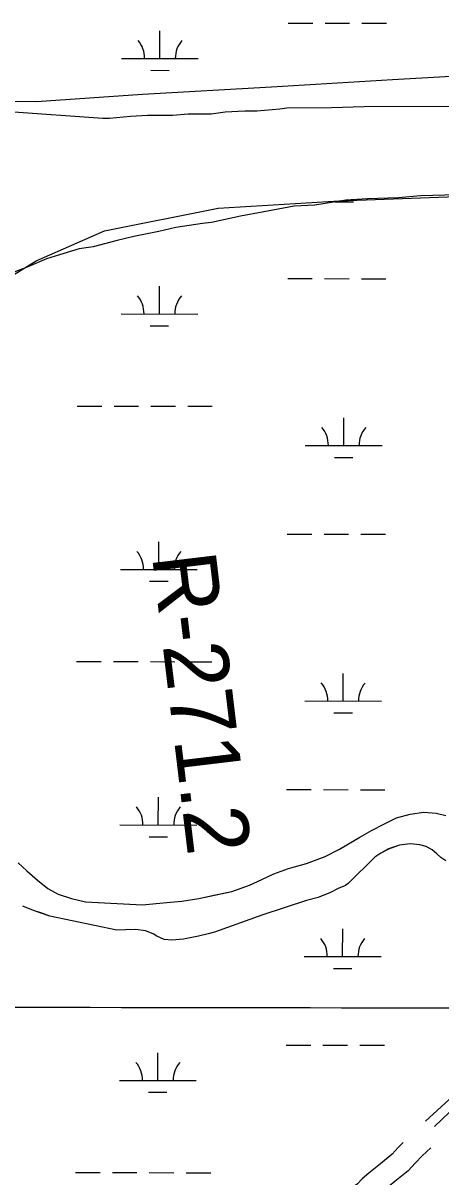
# Model space of a CAD drawing. Extents: x 3219052 to 3256913, y 800770 to 826146.
# Drawn here: x 3227815 to 3228359, y 818080 to 819582 of the extents above; entities that cross this region are included whole.
import ezdxf

# ---------------------------------------------------------------- set-up
doc = ezdxf.new("R2010")
doc.units = 0
for name, color, linetype in [('V-GRID-MAJR', 7, 'Continuous'), ('V-RIVR-RANG-IDEN', 7, 'Continuous'), ('V-ROAD-CNTR', 7, 'Continuous'), ('V-SITE-VEGE', 7, 'Continuous'), ('V-TOPO-SHOR', 7, 'Continuous'), ('V-WETL-SWMP', 7, 'Continuous')]:
    doc.layers.add(name, color=color, linetype=linetype)

msp = doc.modelspace()

# ---------------------------------------------------------------- linework, layer by layer
at = {"layer": 'V-GRID-MAJR'}
msp.add_spline([(3223238.921, 818307.868), (3228474.772, 818299.872), (3233710.625, 818292.637), (3238946.4790000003, 818286.164), (3244182.3340000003, 818280.452), (3249418.1890000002, 818275.502), (3254654.045, 818271.314), (3254654.046, 818271.314)], degree=3, dxfattribs=at)
at = {"layer": 'V-ROAD-CNTR'}
for points in [[(3228410.8688447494, 818221.3545238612), (3228405.7967447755, 818214.4668647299), (3228374.2160611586, 818184.9051391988), (3228338.7016543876, 818152.3343046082)], [(3228350.3662622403, 818145.6356813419), (3228408.5881457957, 818200.9995706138)], [(3228309.642771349, 818124.8571441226), (3228303.2705492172, 818118.2125760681), (3228295.428937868, 818109.459364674), (3228280.1265035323, 818097.0724853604), (3228264.848034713, 818084.8994706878), (3228256.434818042, 818077.5163090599), (3228250.266709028, 818071.0504359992), (3228240.320583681, 818062.8180108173), (3228235.2351730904, 818058.3360911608)], [(3228345.561130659, 818117.8008658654), (3228334.3033871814, 818107.2292102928), (3228325.275450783, 818097.8154239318), (3228316.171062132, 818087.6526353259), (3228298.911496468, 818073.6815146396), (3228284.0999652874, 818061.8805293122), (3228277.2231819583, 818055.8456909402), (3228271.993620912, 818050.3636740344)]]:
    msp.add_lwpolyline(points, dxfattribs=at)
at = {"layer": 'V-SITE-VEGE'}
for p, q in [((3227796.467, 819466.9639999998), (3227918.325, 819458.311)), ((3228059.571, 819463.9799999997), (3228077.708, 819466.634)), ((3228077.708, 819466.634), (3228103.624, 819468.0189999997)), ((3228103.624, 819468.0189999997), (3228119.176, 819468.0719999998)), ((3228119.176, 819468.0719999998), (3228148.977, 819470.767)), ((3228148.977, 819470.767), (3228158.043, 819472.094)), ((3228158.043, 819472.094), (3228216.364, 819472.2929999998)), ((3228216.364, 819472.2929999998), (3228259.128, 819473.7369999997)), ((3228259.128, 819473.737), (3228472.972, 819474.47)), ((3227918.325, 819458.311), (3227927.395, 819458.3420000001)), ((3227927.395, 819458.3420000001), (3227954.605, 819461.027)), ((3227954.605, 819461.0269999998), (3227976.631, 819462.3989999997)), ((3227976.631, 819462.399), (3228009.0330000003, 819462.51)), ((3228009.0330000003, 819462.51), (3228029.765, 819463.8779999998)), ((3228029.765, 819463.8779999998), (3228059.571, 819463.9799999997)), ((3228234.923, 819351.8279999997), (3228194.768, 819345.209)), ((3228263.429, 819353.22), (3228234.923, 819351.828)), ((3228303.603, 819354.656), (3228263.429, 819353.22)), ((3228332.107, 819357.345), (3228303.603, 819354.656)), ((3228380.052, 819358.805), (3228332.107, 819357.345)), ((3228126.111, 819335.8999999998), (3228097.615, 819330.617)), ((3228167.556, 819343.8200000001), (3228126.111, 819335.8999999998)), ((3228194.768, 819345.209), (3228167.556, 819343.8200000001)), ((3228048.397, 819321.3779999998), (3228013.424, 819316.0739999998)), ((3228060.057, 819322.7129999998), (3228048.397, 819321.3779999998)), ((3228097.615, 819330.617), (3228060.057, 819322.7129999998)), ((3227959.031, 819304.2220000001), (3227937.015, 819298.963)), ((3227991.4080000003, 819310.8139999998), (3227959.031, 819304.2220000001)), ((3228013.424, 819316.0739999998), (3227991.4080000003, 819310.8139999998)), ((3227887.801, 819288.426), (3227861.9080000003, 819280.5589999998)), ((3227905.938, 819291.0799999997), (3227887.801, 819288.426)), ((3227937.015, 819298.963), (3227905.938, 819291.0799999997)), ((3227845.078, 819275.3189999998), (3227817.901, 819263.5609999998)), ((3227861.9080000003, 819280.5589999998), (3227845.078, 819275.3189999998)), ((3227817.901, 819263.5609999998), (3227803.663, 819258.3279999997)), ((3228300.93, 818547.5269999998), (3228318.668, 818552.1039999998)), ((3228318.668, 818552.104), (3228336.813, 818554.664)), ((3228336.813, 818554.664), (3228352.656, 818553.6929999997)), ((3228352.656, 818553.6929999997), (3228365.1040000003, 818550.329)), ((3228268.441, 818530.7169999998), (3228285.591, 818539.773)), ((3228285.591, 818539.773), (3228300.93, 818547.5269999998)), ((3228226.87, 818506.4829999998), (3228253.0870000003, 818522.2959999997)), ((3228253.0870000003, 818522.2959999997), (3228268.441, 818530.7169999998)), ((3228208.1520000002, 818497.2319999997), (3228226.87, 818506.4829999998)), ((3228290.774, 818506.8329999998), (3228280.8370000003, 818501.2129999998)), ((3228304.9420000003, 818511.7029999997), (3228290.774, 818506.8329999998)), ((3228318.828, 818513.4500000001), (3228304.9420000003, 818511.7029999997)), ((3228331.316, 818512.3200000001), (3228318.828, 818513.4500000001)), ((3228339.541, 818510.153), (3228331.316, 818512.3200000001)), ((3228347.502, 818505.7559999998), (3228339.541, 818510.1529999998)), ((3228353.664, 818500.724), (3228347.502, 818505.756)), ((3228183.844, 818487.8629999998), (3228208.1520000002, 818497.2319999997)), ((3228272.698, 818496.2289999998), (3228238.091, 818462.033)), ((3228280.8370000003, 818501.2129999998), (3228272.698, 818496.2289999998)), ((3228358.929, 818495.708), (3228353.664, 818500.724)), ((3228365.102, 818491.346), (3228358.929, 818495.708)), ((3227808.079, 818488.9679999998), (3227819.492, 818478.2509999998)), ((3227819.492, 818478.2509999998), (3227833.3370000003, 818466.1460000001)), ((3228141.362, 818474.3699999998), (3228160.49, 818481.6039999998)), ((3228160.49, 818481.6039999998), (3228183.844, 818487.8629999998)), ((3227833.3370000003, 818466.1460000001), (3227846.989, 818455.611)), ((3228109.579, 818459.5609999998), (3228125.588, 818467.2989999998)), ((3228125.588, 818467.299), (3228141.362, 818474.37)), ((3228238.091, 818462.033), (3228234.4620000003, 818459.199)), ((3227846.989, 818455.611), (3227860.477, 818448.2050000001)), ((3227860.477, 818448.2050000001), (3227877.572, 818442.5179999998)), ((3228043.343, 818442.274), (3228086.414, 818451.506)), ((3228086.414, 818451.506), (3228109.579, 818459.561)), ((3228214.855, 818450.1879999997), (3228199.093, 818443.7849999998)), ((3228225.23, 818455.3529999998), (3228214.855, 818450.1879999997)), ((3228234.4620000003, 818459.199), (3228225.23, 818455.3529999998)), ((3227828.342, 818426.699), (3227814.378, 818432.546)), ((3227877.572, 818442.5179999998), (3227895.809, 818438.149)), ((3227895.809, 818438.149), (3227970.356, 818434.2769999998)), ((3227970.356, 818434.2769999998), (3227987.815, 818435.956)), ((3227987.815, 818435.956), (3228006.8370000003, 818437.605)), ((3228006.8370000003, 818437.6049999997), (3228021.609, 818439.1119999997)), ((3228021.609, 818439.112), (3228043.343, 818442.274)), ((3228183.821, 818439.6049999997), (3228126.725, 818421.253)), ((3228199.093, 818443.7849999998), (3228183.821, 818439.6049999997)), ((3227849.6550000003, 818419.5879999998), (3227828.342, 818426.699)), ((3227936.6580000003, 818400.9579999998), (3227849.6550000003, 818419.5879999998)), ((3228126.725, 818421.253), (3228063.96, 818398.5389999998)), ((3227947.843, 818401.6379999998), (3227936.6580000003, 818400.9579999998)), ((3227961.474, 818401.8279999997), (3227947.843, 818401.6379999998)), ((3227973.9590000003, 818400.2490000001), (3227961.474, 818401.828)), ((3227983.934, 818396.262), (3227973.9590000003, 818400.2490000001)), ((3227988.792, 818393.2629999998), (3227983.934, 818396.262)), ((3227998.3200000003, 818389.0649999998), (3227988.792, 818393.2629999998)), ((3228008.576, 818387.9729999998), (3227998.3200000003, 818389.0649999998)), ((3228023.573, 818389.4769999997), (3228008.576, 818387.9729999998)), ((3228043.308, 818393.3449999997), (3228023.573, 818389.4769999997)), ((3228055.872, 818396.235), (3228043.308, 818393.3449999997)), ((3228063.96, 818398.5389999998), (3228055.872, 818396.235))]:
    msp.add_line(p, q, dxfattribs=at)
at = {"layer": 'V-TOPO-SHOR'}
for points in [[(3228790.3889561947, 819487.6412589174), (3228661.164554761, 819487.9121016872), (3228582.221613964, 819497.9480559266), (3228463.8175465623, 819517.9372140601), (3228295.9991486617, 819508.418449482), (3228138.0512043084, 819498.8789973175), (3227970.232806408, 819489.3602327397), (3227832.025769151, 819479.7794054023), (3227703.709873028, 819480.0483440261)], [(3227703.1099330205, 819193.8051911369), (3227831.591329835, 819272.4998808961), (3227920.5081621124, 819311.7955068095), (3228068.6270280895, 819341.0965536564), (3228226.574972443, 819350.6360058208), (3228473.3569987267, 819359.989269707)], [(3227808.079, 818488.968), (3227819.492, 818478.251), (3227833.3370000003, 818466.1460000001), (3227846.989, 818455.611), (3227860.477, 818448.2050000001), (3227877.572, 818442.518), (3227895.809, 818438.149), (3227970.356, 818434.277), (3227987.815, 818435.956), (3228006.8370000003, 818437.605), (3228021.612, 818439.112), (3228043.343, 818442.274), (3228063.309, 818446.585), (3228086.414, 818451.508), (3228109.579, 818459.559), (3228125.588, 818467.299), (3228141.362, 818474.37), (3228160.49, 818481.604), (3228183.844, 818487.863), (3228208.1520000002, 818497.232), (3228226.87, 818506.483), (3228253.0870000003, 818522.296), (3228268.441, 818530.7170000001), (3228285.591, 818539.773), (3228300.93, 818547.527), (3228318.668, 818552.104), (3228336.813, 818554.664), (3228352.656, 818553.693), (3228365.1040000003, 818550.329)], [(3228365.102, 818491.346), (3228358.929, 818495.708), (3228353.662, 818500.724), (3228347.502, 818505.756), (3228339.541, 818510.153), (3228331.316, 818512.3200000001), (3228318.828, 818513.4500000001), (3228304.9420000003, 818511.703), (3228290.774, 818506.833), (3228280.8370000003, 818501.213), (3228272.7, 818496.229), (3228238.091, 818462.033), (3228234.4620000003, 818459.199), (3228225.23, 818455.353), (3228214.855, 818450.188), (3228199.093, 818443.783), (3228183.821, 818439.605), (3228126.725, 818421.253), (3228063.96, 818398.539), (3228055.872, 818396.235), (3228043.308, 818393.345), (3228023.573, 818389.4770000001), (3228008.576, 818387.973), (3227998.3200000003, 818389.063), (3227988.792, 818393.263), (3227983.934, 818396.262), (3227973.957, 818400.2490000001), (3227961.474, 818401.826), (3227947.843, 818401.638), (3227936.6580000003, 818400.958), (3227849.6550000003, 818419.588), (3227840.3310000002, 818422.671), (3227828.344, 818426.697), (3227814.378, 818432.546)]]:
    msp.add_lwpolyline(points, dxfattribs=at)
at = {"layer": 'V-WETL-SWMP'}
for p, q in [((3227992.867298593, 819536.1715655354), (3227992.942748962, 819572.1714542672)), ((3228160.028241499, 819582.2512716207), (3228192.0281711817, 819582.1842026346)), ((3228208.028136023, 819582.1506681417), (3228240.0280657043, 819582.0835991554)), ((3228256.0280305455, 819582.0500646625), (3228288.027960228, 819581.9829956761)), ((3227942.8674084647, 819536.276360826), (3228042.867188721, 819536.0667702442)), ((3227980.8349839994, 819520.7657640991), (3228004.8349312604, 819520.7154623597)), ((3227796.4669837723, 819466.9645471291), (3227918.323984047, 819458.3105547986)), ((3228059.5719833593, 819463.9795356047), (3228077.707983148, 819466.6335296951)), ((3228077.707983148, 819466.6335296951), (3228103.623983, 819468.0185255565)), ((3228103.623983, 819468.0185255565), (3228119.1759829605, 819468.072524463)), ((3228119.1759829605, 819468.0725244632), (3228148.9759827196, 819470.7665177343)), ((3228148.9759827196, 819470.7665177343), (3228158.0429826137, 819472.0935147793)), ((3228158.0429826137, 819472.0935147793), (3228216.363982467, 819472.2935106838)), ((3228216.363982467, 819472.2935106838), (3228259.128982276, 819473.7365053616)), ((3228259.128982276, 819473.7365053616), (3228472.9719817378, 819474.4704903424)), ((3227918.323984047, 819458.3105547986), (3227927.3959840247, 819458.3415541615)), ((3227927.3959840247, 819458.3415541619), (3227954.6039837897, 819461.0275476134)), ((3227954.6039837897, 819461.0275476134), (3227976.6319836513, 819462.3985437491)), ((3227976.6319836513, 819462.3985437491), (3228009.03198357, 819462.5095414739)), ((3228009.03198357, 819462.5095414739), (3228029.7639834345, 819463.877537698)), ((3228029.7639834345, 819463.8775376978), (3228059.5719833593, 819463.9795356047)), ((3228234.9219901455, 819351.826724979), (3228194.767990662, 819345.2087393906)), ((3228220.948458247, 819349.4492853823), (3228244.948405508, 819349.3989836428)), ((3228263.4299899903, 819353.2207206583), (3228234.9219901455, 819351.826724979)), ((3228303.6029898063, 819354.6547155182), (3228263.4299899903, 819353.2207206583)), ((3228332.105989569, 819357.3447088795), (3228303.6029898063, 819354.654715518)), ((3228380.0549893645, 819358.8047031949), (3228332.105989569, 819357.3447088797)), ((3228126.109991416, 819335.9007604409), (3228097.6149918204, 819330.6187717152)), ((3228167.5559908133, 819343.8187436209), (3228126.109991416, 819335.9007604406)), ((3228194.767990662, 819345.2087393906), (3228167.5559908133, 819343.8187436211)), ((3228048.3979925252, 819321.3777913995), (3228013.4229929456, 819316.0728031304)), ((3228060.0569924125, 819322.7137882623), (3228048.3979925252, 819321.3777913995)), ((3228097.6149918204, 819330.6187717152), (3228060.0569924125, 819322.7137882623)), ((3227959.0299938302, 819304.2218278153), (3227937.014994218, 819298.9628386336)), ((3227991.4079933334, 819310.8138139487), (3227959.0299938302, 819304.2218278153)), ((3228013.4229929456, 819316.0728031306), (3227991.4079933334, 819310.8138139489)), ((3227887.801995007, 819288.4248606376), (3227861.9089955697, 819280.5598763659)), ((3227905.9379947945, 819291.0798547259), (3227887.801995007, 819288.4248606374)), ((3227937.014994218, 819298.9628386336), (3227905.9379947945, 819291.0798547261)), ((3227845.077995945, 819275.317886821), (3227817.9019967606, 819263.5609095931)), ((3227861.9089955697, 819280.5598763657), (3227845.077995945, 819275.3178868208)), ((3227817.9019967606, 819263.5609095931), (3227803.6629971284, 819258.3279198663)), ((3228159.3310067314, 819249.5772998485), (3228191.3309364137, 819249.5102308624)), ((3228207.330901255, 819249.4766963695), (3228239.330830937, 819249.4096273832)), ((3228255.3307957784, 819249.3760928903), (3228287.3307254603, 819249.3090239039)), ((3227992.1700638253, 819203.4975937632), (3227992.2455141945, 819239.497482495)), ((3227942.1701736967, 819203.6023890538), (3228042.169953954, 819203.392798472)), ((3227980.1377492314, 819188.0917923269), (3228004.1376964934, 819188.0414905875)), ((3227885.074648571, 819083.6508998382), (3227917.074578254, 819083.5838308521)), ((3227933.0745430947, 819083.5502963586), (3227965.0744727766, 819083.4832273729)), ((3227981.074437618, 819083.4496928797), (3228013.0743673, 819083.3826238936)), ((3228029.074332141, 819083.3490894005), (3228061.0742618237, 819083.2820204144)), ((3228232.283538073, 819032.1811150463), (3228232.358988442, 819068.181003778)), ((3228182.2836479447, 819032.285910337), (3228282.283428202, 819032.0763197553)), ((3228220.2512234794, 819016.7753136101), (3228244.251170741, 819016.7250118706)), ((3228158.6337719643, 818916.9033280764), (3228190.6337016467, 818916.8362590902)), ((3228206.633666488, 818916.8027245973), (3228238.6335961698, 818916.735655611)), ((3228254.6335610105, 818916.7021211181), (3228286.6334906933, 818916.6350521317)), ((3227991.472829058, 818870.823621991), (3227991.548279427, 818906.8235107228)), ((3227941.4729389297, 818870.9284172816), (3228041.472719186, 818870.7188266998)), ((3227979.4405144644, 818855.4178205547), (3228003.440461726, 818855.3675188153)), ((3227884.377413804, 818750.976928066), (3227916.377343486, 818750.9098590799)), ((3227932.377308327, 818750.8763245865), (3227964.3772380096, 818750.8092556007)), ((3227980.3772028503, 818750.7757211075), (3228012.3771325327, 818750.7086521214)), ((3228028.377097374, 818750.6751176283), (3228060.3770270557, 818750.6080486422)), ((3228231.5863033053, 818699.5071432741), (3228231.6617536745, 818735.5070320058)), ((3228181.5864131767, 818699.6119385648), (3228281.586193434, 818699.4023479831)), ((3228219.553988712, 818684.1013418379), (3228243.5539359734, 818684.0510400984)), ((3228157.9365371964, 818584.2293563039), (3228189.9364668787, 818584.1622873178)), ((3228205.93643172, 818584.1287528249), (3228237.936361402, 818584.0616838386)), ((3228253.936326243, 818584.0281493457), (3228285.9362559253, 818583.9610803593)), ((3227990.77559429, 818538.1496502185), (3227990.8510446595, 818574.1495389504)), ((3228300.931204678, 818547.5317120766), (3228318.668204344, 818552.1097027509)), ((3228318.668204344, 818552.1097027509), (3228336.8132041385, 818554.6696970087)), ((3228336.8132041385, 818554.6696970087), (3228352.657204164, 818553.6986977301)), ((3228352.657204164, 818553.6986977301), (3228365.1052043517, 818550.3347029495)), ((3227940.7757041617, 818538.2544455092), (3228040.7754844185, 818538.0448549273)), ((3228268.44020583, 818530.7227442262), (3228285.5912052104, 818539.7797269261)), ((3228285.5912052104, 818539.7797269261), (3228300.931204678, 818547.5317120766)), ((3227978.7432796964, 818522.7438487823), (3228002.7432269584, 818522.6935470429)), ((3228226.8712074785, 818506.4887902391), (3228253.087206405, 818522.3007602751)), ((3228253.087206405, 818522.3007602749), (3228268.44020583, 818530.7227442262)), ((3228208.151208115, 818497.2378079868), (3228226.8712074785, 818506.4887902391)), ((3228290.77520731, 818506.8397855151), (3228280.8372076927, 818501.2187962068)), ((3228304.942206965, 818511.7087758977), (3228290.77520731, 818506.8397855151)), ((3228318.8272068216, 818513.455771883), (3228304.942206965, 818511.7087758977)), ((3228331.3172068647, 818512.3247731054), (3228318.8272068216, 818513.455771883)), ((3228339.542206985, 818510.1577764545), (3228331.3172068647, 818512.3247731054)), ((3228347.502207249, 818505.7617838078), (3228339.542206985, 818510.1577764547)), ((3228353.662207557, 818500.7297924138), (3228347.502207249, 818505.7617838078)), ((3228183.8442087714, 818487.8688263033), (3228208.151208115, 818497.2378079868)), ((3228272.7002080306, 818496.2348056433), (3228238.0912103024, 818462.0398690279)), ((3228280.8372076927, 818501.2187962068), (3228272.7002080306, 818496.2348056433)), ((3228358.929207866, 818495.7148010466), (3228353.662207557, 818500.7297924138)), ((3227808.078209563, 818488.9738484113), (3227819.4922102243, 818478.25686685)), ((3227819.4922102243, 818478.25686685), (3227833.337210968, 818466.1518876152)), ((3228141.3622097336, 818474.37685316), (3228160.4902092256, 818481.609838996)), ((3228160.4902092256, 818481.609838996), (3228183.8442087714, 818487.8688263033)), ((3227833.337210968, 818466.1518876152), (3227846.989211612, 818455.6159055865)), ((3228109.579210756, 818459.564881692), (3228125.5892102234, 818467.3038668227)), ((3228125.5892102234, 818467.3038668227), (3228141.3622097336, 818474.37685316)), ((3228238.0912103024, 818462.0398690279), (3228234.462210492, 818459.2038743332)), ((3227846.989211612, 818455.6159055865), (3227860.4772120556, 818448.2109179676)), ((3227860.4772120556, 818448.2109179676), (3227877.572212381, 818442.5239270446)), ((3228043.3432120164, 818442.2799168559), (3228086.414211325, 818451.5148975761)), ((3228086.414211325, 818451.5148975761), (3228109.579210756, 818459.564881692)), ((3228214.854211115, 818450.1928917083), (3228199.0932115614, 818443.789904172)), ((3228225.22921076, 818455.3578818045), (3228214.854211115, 818450.1928917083)), ((3228234.462210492, 818459.2038743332), (3228225.22921076, 818455.3578818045)), ((3227828.3432135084, 818426.7029584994), (3227814.3792131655, 818432.5529489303)), ((3227877.572212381, 818442.5239270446), (3227895.809212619, 818438.1559336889)), ((3227895.809212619, 818438.1559336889), (3227970.357212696, 818434.2819358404)), ((3227970.357212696, 818434.2819358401), (3227987.8152125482, 818435.961931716)), ((3227987.8152125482, 818435.9619317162), (3228006.837212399, 818437.6109275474)), ((3228006.837212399, 818437.6109275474), (3228021.6112122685, 818439.1179239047)), ((3228021.6112122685, 818439.1179239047), (3228043.3432120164, 818442.2799168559)), ((3228183.8212118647, 818439.6119126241), (3228126.725213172, 818421.2589491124)), ((3228199.0932115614, 818443.789904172), (3228183.8212118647, 818439.6119126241)), ((3227849.656213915, 818419.5949698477), (3227828.3432135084, 818426.7029584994)), ((3227936.658214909, 818400.9629975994), (3227849.656213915, 818419.5949698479)), ((3228126.725213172, 818421.2589491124), (3228063.960214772, 818398.5449937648)), ((3227947.84221484, 818401.6439956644), (3227936.658214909, 818400.9629975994)), ((3227961.4742147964, 818401.8319944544), (3227947.84221484, 818401.6439956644)), ((3227973.956214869, 818400.254996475), (3227961.4742147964, 818401.8319944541)), ((3227983.9342151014, 818396.267002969), (3227973.956214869, 818400.254996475)), ((3228230.889068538, 818366.8331715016), (3228230.9645189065, 818402.8330602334)), ((3227988.7922152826, 818393.2700080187), (3227983.9342151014, 818396.267002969)), ((3227998.31921553, 818389.0680149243), (3227988.7922152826, 818393.2700080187)), ((3228008.575215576, 818387.9790162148), (3227998.31921553, 818389.0680149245)), ((3228023.5732154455, 818389.4820125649), (3228008.575215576, 818387.9790162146)), ((3228043.307215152, 818393.3520043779), (3228023.5732154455, 818389.4820125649)), ((3228055.873214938, 818396.2409984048), (3228043.307215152, 818393.3520043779)), ((3228063.960214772, 818398.5449937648), (3228055.873214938, 818396.2409984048)), ((3228180.8891784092, 818366.9379667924), (3228280.8889586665, 818366.7283762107)), ((3228218.8567539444, 818351.4273700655), (3228242.856701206, 818351.377068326)), ((3228157.2393024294, 818251.5553845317), (3228189.2392321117, 818251.4883155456)), ((3228205.2391969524, 818251.4547810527), (3228237.239126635, 818251.3877120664)), ((3228253.2390914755, 818251.3541775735), (3228285.239021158, 818251.2871085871)), ((3227990.078359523, 818205.4756784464), (3227990.1538098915, 818241.4755671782)), ((3227940.0784693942, 818205.580473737), (3228040.078249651, 818205.3708831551)), ((3227978.046044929, 818190.0698770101), (3228002.0459921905, 818190.0195752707)), ((3227882.9829442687, 818085.6289845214), (3227914.982873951, 818085.5619155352)), ((3227930.982838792, 818085.5283810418), (3227962.982768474, 818085.461312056)), ((3227978.9827333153, 818085.4277775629), (3228010.982662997, 818085.3607085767)), ((3228026.982627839, 818085.3271740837), (3228058.9825575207, 818085.2601050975))]:
    msp.add_line(p, q, dxfattribs=at)
for centre, radius, start, end in [((3227937.6254789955, 819536.762151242), 35.24628790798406, 359.1080939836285, 40.65175231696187), ((3228048.1111084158, 819536.5305832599), 35.246287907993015, 139.10808960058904, 180.65174793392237), ((3227936.928244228, 819204.0881794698), 35.24628790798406, 359.1080939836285, 40.65175231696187), ((3228047.413873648, 819203.8566114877), 35.246287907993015, 139.10808960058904, 180.65174793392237), ((3228177.0417184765, 819032.771700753), 35.24628790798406, 359.1080939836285, 40.65175231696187), ((3228287.527347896, 819032.5401327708), 35.246287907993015, 139.10808960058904, 180.65174793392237), ((3227936.2310094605, 818871.4142076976), 35.24628790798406, 359.1080939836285, 40.65175231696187), ((3228046.716638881, 818871.1826397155), 35.246287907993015, 139.10808960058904, 180.65174793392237), ((3228176.3444837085, 818700.0977289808), 35.24628790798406, 359.1080939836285, 40.65175231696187), ((3228286.8301131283, 818699.8661609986), 35.246287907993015, 139.10808960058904, 180.65174793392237), ((3227935.5337746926, 818538.7402359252), 35.24628790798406, 359.1080939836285, 40.65175231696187), ((3228046.019404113, 818538.5086679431), 35.246287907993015, 139.10808960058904, 180.65174793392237), ((3228175.647248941, 818367.4237572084), 35.24628790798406, 359.1080939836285, 40.65175231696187), ((3228286.132878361, 818367.1921892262), 35.246287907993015, 139.10808960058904, 180.65174793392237), ((3227934.8365399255, 818206.066264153), 35.24628790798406, 359.1080939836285, 40.65175231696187), ((3228045.3221693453, 818205.8346961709), 35.246287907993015, 139.10808960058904, 180.65174793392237)]:
    msp.add_arc(centre, radius, start, end, dxfattribs=at)

# ---------------------------------------------------------------- texts
at = {"layer": 'V-RIVR-RANG-IDEN'}
msp.add_text('R-271.2', height=82.99999799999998, rotation=276.8554094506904, dxfattribs=at).set_placement((3227982.471, 818888.344))

doc.saveas('drawing.dxf')
